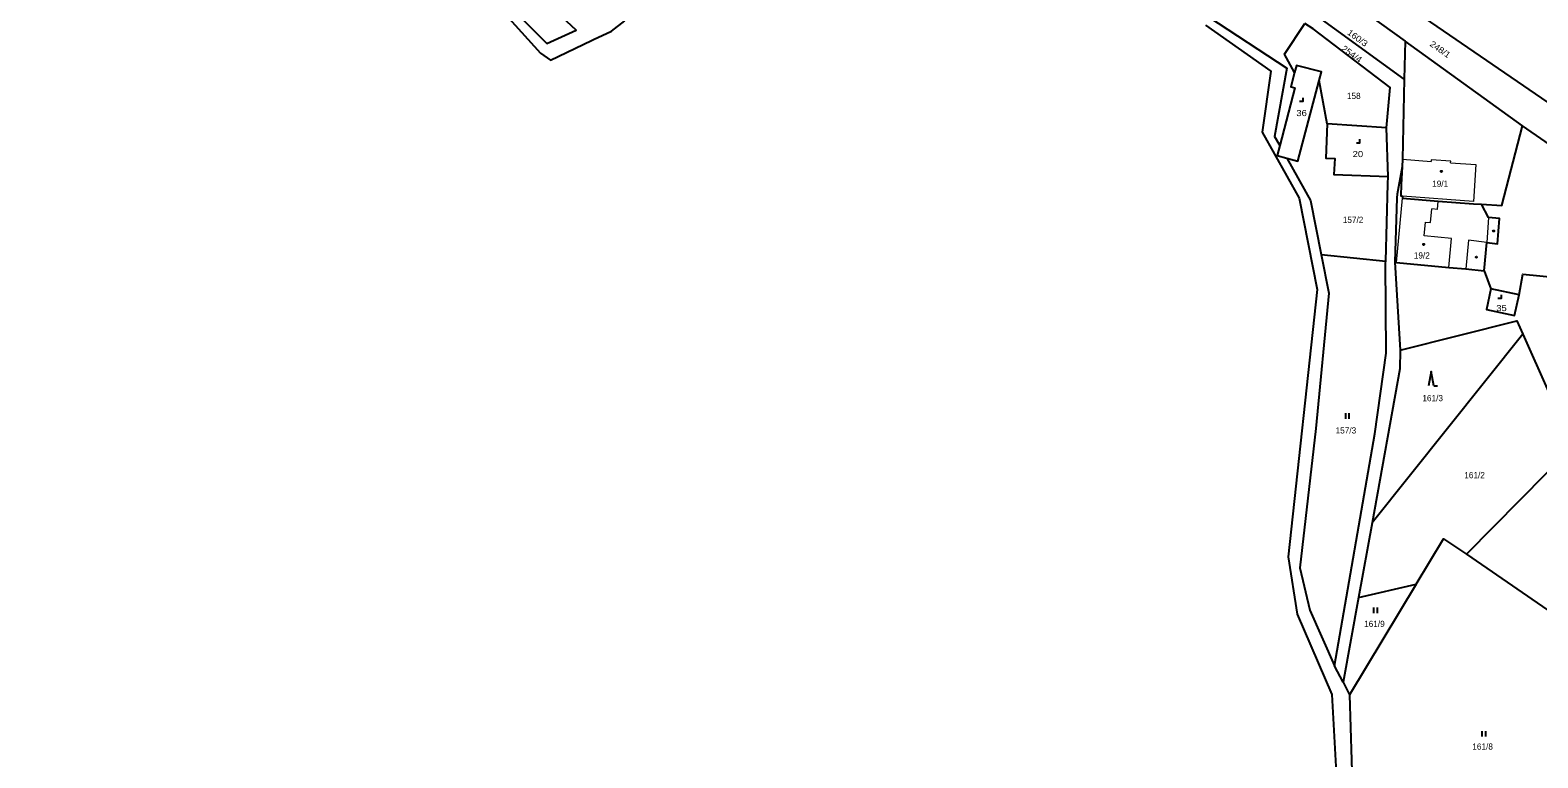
# Model space of a CAD drawing. Extents: x -632162 to -629607, y -1101195 to -1098670.
# Drawn here: x -632089.1 to -631672.5, y -1099752.9 to -1099551.6 of the extents above; entities that cross this region are included whole.
import ezdxf
from ezdxf.enums import TextEntityAlignment as Align

# ---------------------------------------------------------------- set-up
doc = ezdxf.new("R2010")
doc.units = 0
doc.header["$LTSCALE"] = 0.68
for name, color, linetype, lineweight in [('1', 7, 'Continuous', 25), ('3', 7, 'Continuous', 25), ('4', 7, 'Continuous', 13), ('5', 7, 'Continuous', 25)]:
    doc.layers.add(name, color=color, linetype=linetype, lineweight=lineweight)
doc.layers.add('2', color=7, linetype='Continuous')

msp = doc.modelspace()

# ---------------------------------------------------------------- linework, layer by layer
at = {"layer": '1'}
for p, q in [((-631728.72, -1099540.48), (-631709.18, -1099554.6)), ((-631709.42, -1099565.08), (-631734.34, -1099547.04)), ((-631707.18, -1099545.97), (-631635.13, -1099595.26)), ((-631730.75, -1099577.49), (-631732.95, -1099565.53)), ((-631714.33, -1099578.61), (-631730.75, -1099577.49)), ((-631642.83, -1099601.66), (-631676.76, -1099578.04)), ((-631713.84, -1099592.08), (-631714.33, -1099578.61)), ((-631712.07, -1099615.77), (-631710.55, -1099640.09)), ((-631687.33, -1099618.1), (-631685.46, -1099623.09)), ((-631677.69, -1099624.77), (-631685.46, -1099623.09)), ((-631706.16, -1099704.83), (-631724.52, -1099735.45)), ((-631726.32, -1099731.94), (-631728.66, -1099727.36))]:
    msp.add_line(p, q, dxfattribs=at)
for points in [[(-632089.14, -1099414.94), (-632087.35, -1099435.69), (-632086.01, -1099445.85), (-632077.01, -1099455.99), (-632061.08, -1099490.08), (-632048.45, -1099504.28), (-632032.48, -1099509.93), (-631984.42, -1099522.73), (-631966.13, -1099535.27), (-631946.34, -1099555.29), (-631938.25, -1099551.55), (-631978.6, -1099513.97)], [(-631967.38, -1099536.57), (-631948.1, -1099557.91), (-631945.37, -1099559.83), (-631933.99, -1099554.41), (-631933.45, -1099554.15), (-631928.51, -1099551.8), (-631924.83, -1099548.94)], [(-631805.5, -1099534.69), (-631771.51, -1099545.34), (-631763.53, -1099547.84), (-631741.87, -1099562.08), (-631745.26, -1099581.01), (-631743.85, -1099583.51)], [(-631764.34, -1099550.18), (-631746.33, -1099562.91), (-631748.65, -1099579.78), (-631738.45, -1099598.01), (-631733.47, -1099623.28), (-631741.47, -1099697.22), (-631739.03, -1099713.08), (-631729.4, -1099735.3), (-631727.98, -1099761.86)], [(-631739.71, -1099563.27), (-631742.52, -1099558.16), (-631736.87, -1099549.74)], [(-631714.33, -1099578.61), (-631713.3, -1099567.42), (-631734.63, -1099551.23), (-631736.87, -1099549.74)], [(-631676.76, -1099578.04), (-631709.18, -1099554.6), (-631709.42, -1099565.08)], [(-631732.95, -1099565.53), (-631732.31, -1099563.12), (-631739.21, -1099561.35), (-631739.71, -1099563.27)], [(-631739.71, -1099563.27), (-631740.73, -1099567.2), (-631739.62, -1099567.5), (-631743.85, -1099583.51)], [(-631741.91, -1099586.95), (-631738.82, -1099587.77), (-631732.95, -1099565.53)], [(-631709.42, -1099565.08), (-631709.93, -1099587.27), (-631710.02, -1099589.41)], [(-631730.75, -1099577.49), (-631731.11, -1099586.94), (-631728.57, -1099587.11), (-631728.86, -1099591.45), (-631713.84, -1099592.08)], [(-631688.11, -1099599.68), (-631682.45, -1099600.1), (-631676.76, -1099578.04)], [(-631743.85, -1099583.51), (-631744.57, -1099586.25), (-631741.91, -1099586.95)], [(-631741.91, -1099586.95), (-631735.31, -1099598.66), (-631732.39, -1099613.6), (-631714.55, -1099615.5)], [(-631710.02, -1099589.41), (-631711.42, -1099596.92), (-631711.46, -1099597.94), (-631712.07, -1099615.77)], [(-631710.02, -1099589.41), (-631710.24, -1099594.24), (-631710.38, -1099597.43), (-631709.88, -1099597.47), (-631709.94, -1099598.07), (-631700.01, -1099598.83), (-631690.33, -1099599.57), (-631688.11, -1099599.68)], [(-631714.55, -1099615.5), (-631713.92, -1099594.08), (-631713.84, -1099592.08)], [(-631687.33, -1099618.1), (-631686.62, -1099610.31), (-631683.66, -1099610.65), (-631683.06, -1099603.66), (-631686.16, -1099603.39), (-631688.11, -1099599.68)], [(-631677.69, -1099624.77), (-631676.66, -1099619.1), (-631660.7, -1099620.6), (-631642.83, -1099601.66)], [(-631732.39, -1099613.6), (-631730.3, -1099624.29), (-631733.83, -1099661.75), (-631738.25, -1099700.28), (-631735.55, -1099712.01), (-631728.66, -1099727.36)], [(-631728.66, -1099727.36), (-631717.59, -1099663.19), (-631714.43, -1099640.87), (-631714.56, -1099616), (-631714.55, -1099615.5)], [(-631712.07, -1099615.77), (-631711.57, -1099615.82), (-631697.1, -1099617.18), (-631692.42, -1099617.62), (-631687.33, -1099618.1)], [(-631685.46, -1099623.09), (-631686.7, -1099628.85), (-631678.93, -1099630.53), (-631677.69, -1099624.77)], [(-631710.55, -1099640.09), (-631678.32, -1099631.94), (-631676.68, -1099635.62)], [(-631676.68, -1099635.62), (-631718.25, -1099687.87), (-631722.04, -1099708.54), (-631706.16, -1099704.83)], [(-631676.68, -1099635.62), (-631662.84, -1099666.69), (-631692.22, -1099696.53)], [(-631710.55, -1099640.09), (-631710.69, -1099645.25), (-631718.25, -1099687.87)], [(-631692.22, -1099696.53), (-631646.04, -1099728.34), (-631586.86, -1099640.17)], [(-631706.16, -1099704.83), (-631698.61, -1099692.24), (-631692.22, -1099696.53)], [(-631722.04, -1099708.54), (-631726.32, -1099731.94), (-631724.52, -1099735.45)], [(-631724.52, -1099735.45), (-631723.73, -1099762.52), (-631729.47, -1099777.53), (-631727.37, -1099785.28), (-631689.19, -1099797.05), (-631674.85, -1099808.29)]]:
    msp.add_lwpolyline(points, dxfattribs=at)
at = {"layer": '3'}
for p, q in [((-631701.25, -1099649.95), (-631700.254, -1099649.95)), ((-631725.611, -1099659.05), (-631725.611, -1099657.55)), ((-631724.61, -1099659.05), (-631724.61, -1099657.55)), ((-631717.851, -1099712.81), (-631717.851, -1099711.31)), ((-631716.85, -1099712.81), (-631716.85, -1099711.31)), ((-631687.881, -1099746.97), (-631687.881, -1099745.47)), ((-631686.88, -1099746.97), (-631686.88, -1099745.47))]:
    msp.add_line(p, q, dxfattribs=at)
for points in [[(-631738.401, -1099571.24), (-631737.4, -1099571.24), (-631737.4, -1099570.24)], [(-631722.661, -1099582.72), (-631721.66, -1099582.72), (-631721.66, -1099581.72)], [(-631683.581, -1099625.74), (-631682.58, -1099625.74), (-631682.58, -1099624.74)], [(-631701.25, -1099649.95), (-631702, -1099645.95), (-631702.75, -1099649.95)]]:
    msp.add_lwpolyline(points, dxfattribs=at)
at = {"layer": '4'}
for p, q in [((-631709.93, -1099587.27), (-631702.02, -1099587.85)), ((-631701.99, -1099587.45), (-631702.02, -1099587.85)), ((-631696.58, -1099587.84), (-631701.99, -1099587.45)), ((-631696.61, -1099588.24), (-631696.58, -1099587.84)), ((-631696.61, -1099588.24), (-631689.6, -1099588.75)), ((-631689.6, -1099588.75), (-631690.29, -1099598.97)), ((-631711.57, -1099615.82), (-631709.94, -1099598.07)), ((-631690.29, -1099598.97), (-631709.88, -1099597.47)), ((-631700.23, -1099601.18), (-631700.01, -1099598.83)), ((-631702.18, -1099604.77), (-631701.82, -1099601.03)), ((-631700.23, -1099601.18), (-631701.82, -1099601.03)), ((-631703.88, -1099608.49), (-631703.52, -1099604.65)), ((-631703.52, -1099604.65), (-631702.18, -1099604.77)), ((-631696.35, -1099609.2), (-631703.88, -1099608.49)), ((-631697.1, -1099617.18), (-631696.35, -1099609.2)), ((-631691.7, -1099609.69), (-631692.42, -1099617.62))]:
    msp.add_line(p, q, dxfattribs=at)
msp.add_lwpolyline([(-631686.16, -1099603.39), (-631686.62, -1099610.31), (-631691.7, -1099609.69)], dxfattribs=at)
at = {"layer": '5'}
for centre in [(-631699.1668, -1099590.6292), (-631684.7268, -1099607.1292), (-631704.0668, -1099610.8292), (-631689.4968, -1099614.3592)]:
    msp.add_circle(centre, 0.175, dxfattribs=at)

# ---------------------------------------------------------------- texts
at = {"layer": '2', "width": 1.1}
for s, rotation, p in [('160/3', 324, (-631722.8266, -1099554.4089)), ('254/4', 324, (-631724.4066, -1099558.8389)), ('248/1', 325, (-631699.9625, -1099557.5831))]:
    msp.add_text(s, height=1.7, rotation=rotation, dxfattribs=at).set_placement(p, align=Align.CENTER)
at = {"layer": '2'}
for s, p in [('158', (-631723.369, -1099570.6)), ('19/1', (-631699.5, -1099594.88)), ('157/2', (-631723.57, -1099604.87)), ('19/2', (-631704.57, -1099614.73)), ('161/3', (-631701.57, -1099654.2)), ('157/3', (-631725.55, -1099663.13)), ('161/2', (-631689.99, -1099675.51)), ('161/9', (-631717.67, -1099716.65)), ('161/8', (-631687.77, -1099750.58))]:
    msp.add_text(s, height=1.7, dxfattribs=at).set_placement(p, align=Align.CENTER)
at = {"layer": '2', "width": 1.15}
for s, p in [('36', (-631737.8, -1099575.34)), ('20', (-631722.23, -1099586.69)), ('35', (-631682.55, -1099629.28))]:
    msp.add_text(s, height=1.7, dxfattribs=at).set_placement(p, align=Align.CENTER)

doc.saveas('drawing.dxf')
